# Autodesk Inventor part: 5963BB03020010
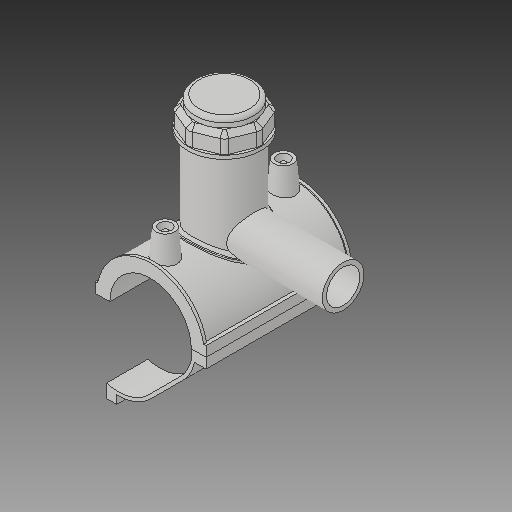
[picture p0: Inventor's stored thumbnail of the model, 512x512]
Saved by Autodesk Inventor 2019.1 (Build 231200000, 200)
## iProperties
Created: 2017-07
Part Number: 5963BB03020010
Material: Generic
Description: PLASSON TAPPING SADDLE 2''IPS x 1''IPS
Document SubType Name: Modeling
Designer: KIM
Mass: 1712.7 g
Surface Area: 2671.49 cm^2
Volume: 1712.7 cm^3
Density: 1 g/cm^3
Appearance: Default
Author: KIM
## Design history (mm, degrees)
derived "5963B.ipt"
feature "Solid1::5963B.ipt"
feature "Solid2::5963B.ipt"
feature "Solid4::5963B.ipt"
feature "Solid5::5963B.ipt"
tag "TaggingFeature1"
body "Solid1"
body "Solid2"
other parameters: "d0" = 65.1, "d2" = 88.9, "d3" = 16.275, "d4" = 118.11, "d5" = 0, "d6" = 0.1, "d8" = 0, "d19" = 6, "d20" = 6, "d21" = 70.866, "d23" = 0, "d24" = 35.433, "d26" = 0, "d29" = 3, "d30" = 21.7, "d31" = 6, "d32" = 0, "d33" = 0, "d34" = 0.6, "d40" = 44.0076, "d41" = 58.59, "d43" = 0, "d45" = 0, "d47" = 113.181, "d70" = 15, "d72" = 0, "d73" = 6, "d75" = 5, "d76" = 0, "d77" = 3.255, "d78" = 62.55, "d79" = 15, "d80" = 47.244, "d82" = 5 deg, "d84" = 4, "d85" = 14, "d86" = 0, "d87" = 3, "d88" = 0, "d89" = 1, "d90" = 1, "d91" = 94.488, "d92" = 0, "d93" = 0.5, "d94" = 34.26316, "d96" = 86.3226, "d97" = 2.3622, "d98" = 0, "d102" = 0.651, "d120" = 140 deg, "d121" = 24.228, "d122" = 20 deg, "d123" = 169.26, "d124" = 50.778, "d126" = 0, "d143" = 67.053, "d145" = 15.02308, "d149" = 0.9765, "d150" = 16.52538, "d153" = 118.11, "d154" = 0, "d156" = 42.315, "d157" = 160 deg, "d159" = 3.906, "d161" = 0.9765, "d162" = 70.866, "d163" = 0, "d164" = 32.55, "d167" = 6.51, "d168" = 41.28293, "d170" = 3.2805, "d172" = 0, "d173" = 1, "d175" = 32.55, "d176" = 20 deg, "d177" = 4.557, "d178" = 19.53, "d180" = 0, "d183" = 7.812, "d184" = 3.6456, "d185" = 38.38575, "d186" = 38.38575, "d187" = 42.315, "d188" = 5.859, "d189" = 4.557, "d190" = 0, "d191" = 63.4725, "d193" = 6.1236, "d194" = 4.13385, "d195" = 90 deg, "d197" = 0, "d199" = 0, "d200" = 9.765, "d202" = 0, "d203" = 98.044, "d204" = 55.6605, "d205" = 41.013, "d206" = 49.8015, "d207" = 73.533, "d208" = 76.47432, "d209" = 91.18092, "d210" = 50.3874, "d211" = 58.59, "d212" = 46.872, "d213" = -3.7836, "d216" = 0, "d217" = 6.51, "d218" = 3.255, "d219" = 0.651, "d222" = 65.1, "d224" = 0, "d230" = 3.906, "d233" = 6, "d236" = 44.45, "d237" = 35.433, "d238" = 6.02433, "d240" = 35.433, "d241" = 35.433, "d242" = 35.433, "d243" = 6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
